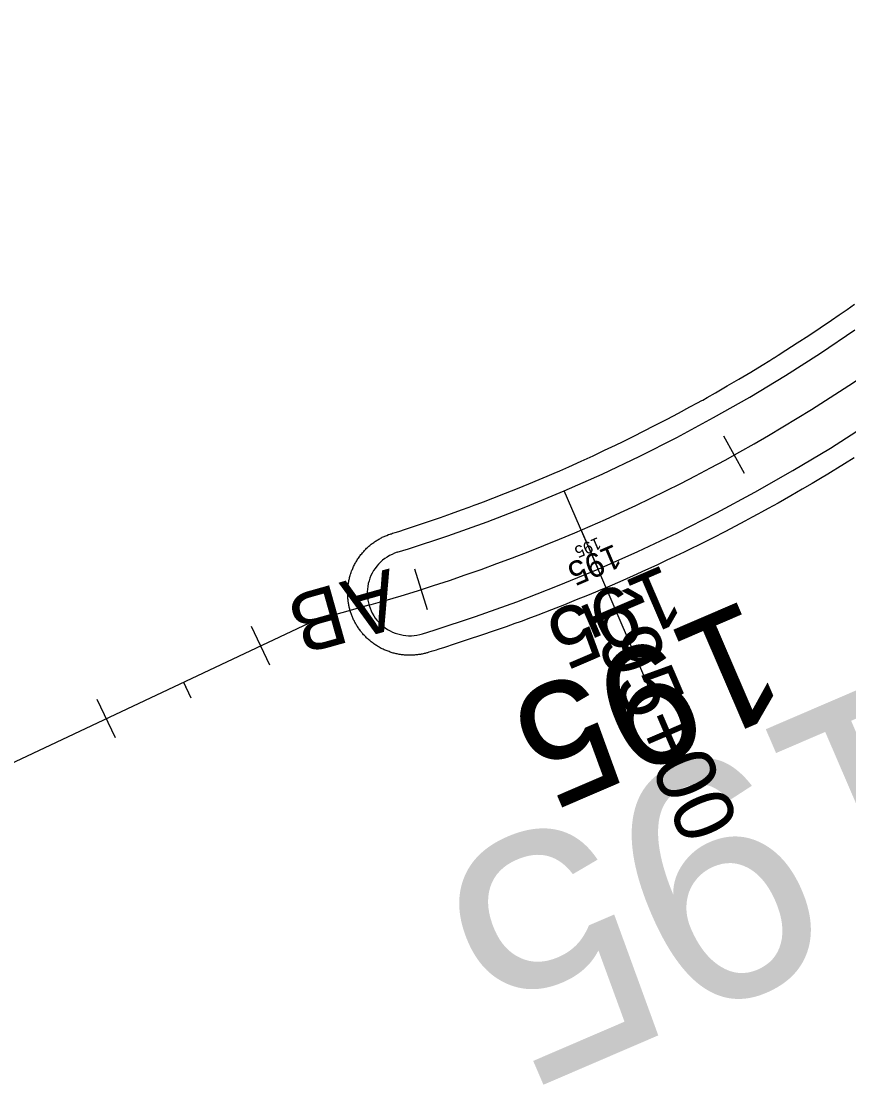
# Model space of a CAD drawing. Extents: x 1823824 to 1861612, y 706975 to 726130.
# Drawn here: x 1825801.7 to 1825898.7, y 712728.7 to 712853.4 of the extents above; entities that cross this region are included whole.
import ezdxf

# ---------------------------------------------------------------- set-up
doc = ezdxf.new("R2010")
doc.units = 0
for name, color, linetype in [('DR_X_Flood_Boundary', 7, 'Continuous'), ('GE_X_CL_10', 7, 'Continuous'), ('GE_X_CL_100', 7, 'Continuous'), ('GE_X_CL_20', 7, 'Continuous'), ('GE_X_CL_200', 7, 'Continuous'), ('GE_X_CL_50', 7, 'Continuous'), ('SC_Scratch2', 7, 'Continuous'), ('SC_Scratch5', 7, 'Continuous'), ('SC_Scratch6', 7, 'Continuous')]:
    doc.layers.add(name, color=color, linetype=linetype)

msp = doc.modelspace()

# ---------------------------------------------------------------- linework, layer by layer
at = {"layer": 'DR_X_Flood_Boundary'}
for p, q in [((1825842.46, 712784.93), (1825836.12, 712783.15)), ((1825836.12, 712783.15), (1825768.62, 712751.29))]:
    msp.add_line(p, q, dxfattribs=at)
msp.add_arc((1825788.29, 712977.46), 200, 285.7144, 321.6626, dxfattribs=at)
at = {"layer": 'GE_X_CL_10'}
for p, q in [((1825867.32, 712793.74), (1825867.72, 712792.82)), ((1825820.73, 712775.89), (1825821.15, 712774.98))]:
    msp.add_line(p, q, dxfattribs=at)
at = {"layer": 'GE_X_CL_100'}
msp.add_line((1825867.32, 712793.74), (1825871.27, 712784.55), dxfattribs=at)
at = {"layer": 'GE_X_CL_20'}
for p, q in [((1825867.32, 712793.74), (1825868.11, 712791.9)), ((1825820.73, 712775.89), (1825821.58, 712774.08))]:
    msp.add_line(p, q, dxfattribs=at)
at = {"layer": 'GE_X_CL_200'}
msp.add_line((1825867.32, 712793.74), (1825875.22, 712775.36), dxfattribs=at)
at = {"layer": 'GE_X_CL_50'}
msp.add_line((1825867.32, 712793.74), (1825869.3, 712789.14), dxfattribs=at)
at = {"layer": 'SC_Scratch2'}
for p, q in [((1825896.53, 712803.36), (1825900.85, 712806.12)), ((1825892.14, 712800.71), (1825896.53, 712803.36)), ((1825887.69, 712798.17), (1825892.14, 712800.71)), ((1825883.18, 712795.74), (1825887.69, 712798.17)), ((1825878.61, 712793.43), (1825883.18, 712795.74)), ((1825873.98, 712791.23), (1825878.61, 712793.43)), ((1825869.3, 712789.14), (1825873.98, 712791.23)), ((1825864.56, 712787.18), (1825869.3, 712789.14)), ((1825859.78, 712785.33), (1825864.56, 712787.18)), ((1825854.96, 712783.6), (1825859.78, 712785.33)), ((1825850.09, 712782), (1825854.96, 712783.6)), ((1825848.73, 712781.57), (1825850.09, 712782))]:
    msp.add_line(p, q, dxfattribs=at)
for points in [[(1825844.75, 712793.2), (1825844.96, 712793.27), (1825845.03, 712793.29), (1825845.07, 712793.31), (1825845.09, 712793.31), (1825845.24, 712793.36), (1825845.52, 712793.45), (1825845.95, 712793.59), (1825846.74, 712793.85), (1825847.9, 712794.23), (1825849.43, 712794.74), (1825850.84, 712795.22), (1825852.13, 712795.67), (1825853.3, 712796.1), (1825854.19, 712796.42), (1825854.81, 712796.64), (1825855.15, 712796.77), (1825855.87, 712797.04), (1825856.98, 712797.47), (1825858.47, 712798.05), (1825859.88, 712798.61), (1825861.2, 712799.15), (1825862.42, 712799.67), (1825863.33, 712800.05), (1825863.9, 712800.29), (1825864.16, 712800.4), (1825864.81, 712800.69), (1825865.88, 712801.16), (1825867.34, 712801.82), (1825868.74, 712802.46), (1825870.08, 712803.09), (1825871.35, 712803.7), (1825872.26, 712804.13), (1825872.8, 712804.39), (1825872.97, 712804.47), (1825873.56, 712804.77), (1825874.57, 712805.29), (1825876, 712806.02), (1825877.4, 712806.74), (1825878.75, 712807.46), (1825880.06, 712808.17), (1825880.97, 712808.67), (1825881.48, 712808.94), (1825881.57, 712808.99), (1825882.1, 712809.29), (1825883.06, 712809.84), (1825884.45, 712810.64), (1825885.82, 712811.45), (1825887.19, 712812.27), (1825888.54, 712813.09), (1825889.44, 712813.64), (1825889.91, 712813.92), (1825889.93, 712813.93), (1825890.39, 712814.23), (1825891.3, 712814.82), (1825892.65, 712815.68), (1825893.99, 712816.56), (1825895.32, 712817.46), (1825896.65, 712818.36), (1825897.54, 712818.97), (1825898.01, 712819.28), (1825898.04, 712819.3), (1825898.48, 712819.62), (1825899.34, 712820.24)], [(1825845.78, 712791.13), (1825847.08, 712791.53), (1825851.71, 712793.06), (1825856.3, 712794.7), (1825860.84, 712796.46), (1825865.35, 712798.33), (1825869.8, 712800.31), (1825874.2, 712802.4), (1825878.55, 712804.61), (1825882.84, 712806.92), (1825887.08, 712809.33), (1825891.25, 712811.86), (1825895.36, 712814.48), (1825899.4, 712817.21)], [(1825899.31, 712802.21), (1825898.18, 712801.5), (1825897.36, 712800.99), (1825896.87, 712800.69), (1825896.21, 712800.3), (1825895.38, 712799.8), (1825894.4, 712799.21), (1825893.24, 712798.53), (1825891.9, 712797.76), (1825890.4, 712796.91), (1825889.25, 712796.27), (1825888.46, 712795.83), (1825888.03, 712795.59), (1825887.37, 712795.24), (1825886.5, 712794.78), (1825885.41, 712794.2), (1825884.17, 712793.55), (1825882.78, 712792.84), (1825881.24, 712792.06), (1825880.08, 712791.49), (1825879.32, 712791.11), (1825878.95, 712790.94), (1825878.3, 712790.63), (1825877.38, 712790.2), (1825876.19, 712789.64), (1825874.87, 712789.03), (1825873.42, 712788.38), (1825871.84, 712787.68), (1825870.68, 712787.17), (1825869.96, 712786.86), (1825869.65, 712786.73), (1825869.02, 712786.47), (1825868.06, 712786.07), (1825866.76, 712785.54), (1825865.36, 712784.98), (1825863.85, 712784.39), (1825862.24, 712783.77), (1825861.09, 712783.33), (1825860.4, 712783.07), (1825860.17, 712782.99), (1825859.55, 712782.77), (1825858.54, 712782.41), (1825857.14, 712781.92), (1825855.66, 712781.41), (1825854.1, 712780.89)], [(1825840.45, 712783.74), (1825840.41, 712783.84), (1825840.37, 712783.94), (1825840.34, 712784.05), (1825840.3, 712784.15), (1825840.27, 712784.25), (1825840.24, 712784.36), (1825840.21, 712784.46), (1825840.19, 712784.57), (1825840.16, 712784.68), (1825840.13, 712784.78), (1825840.11, 712784.89), (1825840.09, 712785), (1825840.07, 712785.11), (1825840.05, 712785.23), (1825840.04, 712785.34), (1825840.02, 712785.45), (1825840.01, 712785.56), (1825840, 712785.67), (1825839.99, 712785.75), (1825839.98, 712785.79), (1825839.98, 712785.79), (1825839.98, 712785.83), (1825839.98, 712785.91), (1825839.97, 712786.03), (1825839.97, 712786.15), (1825839.97, 712786.26), (1825839.96, 712786.38), (1825839.97, 712786.5), (1825839.97, 712786.62), (1825839.98, 712786.74), (1825839.98, 712786.86), (1825839.99, 712786.98), (1825840, 712787.1), (1825840.02, 712787.22), (1825840.03, 712787.34), (1825840.05, 712787.46), (1825840.07, 712787.58), (1825840.09, 712787.7), (1825840.12, 712787.83), (1825840.14, 712787.95), (1825840.17, 712788.07), (1825840.2, 712788.19), (1825840.23, 712788.31), (1825840.27, 712788.43), (1825840.3, 712788.55), (1825840.34, 712788.66), (1825840.38, 712788.78), (1825840.43, 712788.9), (1825840.47, 712789.02), (1825840.52, 712789.13), (1825840.57, 712789.25), (1825840.62, 712789.36), (1825840.67, 712789.48), (1825840.73, 712789.59), (1825840.78, 712789.7), (1825840.84, 712789.82), (1825840.9, 712789.93), (1825840.96, 712790.03), (1825841.03, 712790.14), (1825841.1, 712790.25), (1825841.16, 712790.35), (1825841.23, 712790.46), (1825841.31, 712790.56), (1825841.38, 712790.66), (1825841.45, 712790.76), (1825841.53, 712790.86), (1825841.61, 712790.96), (1825841.69, 712791.06), (1825841.77, 712791.15), (1825841.85, 712791.24), (1825841.93, 712791.33), (1825842.02, 712791.42), (1825842.11, 712791.51), (1825842.19, 712791.6), (1825842.28, 712791.68), (1825842.37, 712791.76), (1825842.46, 712791.84), (1825842.56, 712791.92), (1825842.65, 712792), (1825842.74, 712792.08), (1825842.84, 712792.15), (1825842.93, 712792.22), (1825843.03, 712792.29), (1825843.13, 712792.36), (1825843.23, 712792.43), (1825843.32, 712792.49), (1825843.42, 712792.55), (1825843.52, 712792.61), (1825843.62, 712792.67), (1825843.73, 712792.73), (1825843.83, 712792.78), (1825843.93, 712792.84), (1825844.03, 712792.89), (1825844.13, 712792.94), (1825844.24, 712792.99), (1825844.34, 712793.03), (1825844.44, 712793.08), (1825844.54, 712793.12), (1825844.75, 712793.2)], [(1825854.1, 712780.89), (1825852.45, 712780.35), (1825851.31, 712779.98), (1825850.67, 712779.77), (1825850.52, 712779.72), (1825850.32, 712779.66), (1825850.06, 712779.58), (1825849.74, 712779.48), (1825849.49, 712779.41), (1825849.33, 712779.35), (1825849.23, 712779.33), (1825849.14, 712779.3), (1825849.04, 712779.28), (1825848.93, 712779.25), (1825848.82, 712779.23), (1825848.71, 712779.2), (1825848.6, 712779.18), (1825848.49, 712779.16), (1825848.38, 712779.14), (1825848.27, 712779.13), (1825848.16, 712779.11), (1825848.04, 712779.1), (1825847.93, 712779.09), (1825847.81, 712779.08), (1825847.7, 712779.07), (1825847.58, 712779.06), (1825847.46, 712779.06), (1825847.34, 712779.06), (1825847.23, 712779.06), (1825847.11, 712779.06), (1825846.99, 712779.06), (1825846.87, 712779.07), (1825846.75, 712779.07), (1825846.63, 712779.08), (1825846.51, 712779.1), (1825846.39, 712779.11), (1825846.26, 712779.12), (1825846.14, 712779.14), (1825846.02, 712779.16), (1825845.9, 712779.18), (1825845.78, 712779.21), (1825845.66, 712779.23), (1825845.54, 712779.26), (1825845.42, 712779.29), (1825845.3, 712779.32), (1825845.18, 712779.36), (1825845.06, 712779.4), (1825844.94, 712779.43), (1825844.82, 712779.48), (1825844.71, 712779.52), (1825844.59, 712779.56), (1825844.47, 712779.61), (1825844.36, 712779.66), (1825844.24, 712779.71), (1825844.13, 712779.76), (1825844.02, 712779.82), (1825843.9, 712779.87), (1825843.79, 712779.93), (1825843.68, 712779.99), (1825843.57, 712780.06), (1825843.46, 712780.12), (1825843.36, 712780.19), (1825843.25, 712780.26), (1825843.15, 712780.33), (1825843.04, 712780.4), (1825842.94, 712780.47), (1825842.84, 712780.55), (1825842.74, 712780.62), (1825842.65, 712780.7), (1825842.55, 712780.78), (1825842.46, 712780.86), (1825842.36, 712780.94), (1825842.27, 712781.03), (1825842.18, 712781.11), (1825842.1, 712781.2), (1825842.01, 712781.29), (1825841.93, 712781.37), (1825841.84, 712781.46), (1825841.76, 712781.56), (1825841.68, 712781.65), (1825841.61, 712781.74), (1825841.53, 712781.83), (1825841.46, 712781.93), (1825841.38, 712782.03), (1825841.31, 712782.12), (1825841.25, 712782.22), (1825841.18, 712782.32), (1825841.12, 712782.42), (1825841.05, 712782.52), (1825840.99, 712782.62), (1825840.93, 712782.72), (1825840.88, 712782.82), (1825840.82, 712782.92), (1825840.77, 712783.02), (1825840.72, 712783.12), (1825840.67, 712783.22), (1825840.62, 712783.33), (1825840.57, 712783.43), (1825840.53, 712783.53), (1825840.49, 712783.64), (1825840.45, 712783.74)]]:
    msp.add_lwpolyline(points, dxfattribs=at)
msp.add_arc((1825847.26, 712786.35), 5, 107.1437, 287.1451, dxfattribs=at)
at = {"layer": 'SC_Scratch5'}
for points in [[(1825886.48, 712800.36), (1825884.06, 712804.73)], [(1825869.3, 712789.14), (1825865.35, 712798.33)], [(1825849.34, 712784.38), (1825847.83, 712789.15)], [(1825830.84, 712777.89), (1825828.7, 712782.42)], [(1825812.75, 712769.36), (1825810.62, 712773.88)]]:
    msp.add_lwpolyline(points, dxfattribs=at)

# ---------------------------------------------------------------- texts
at = {"layer": 'GE_X_CL_10'}
msp.add_text('195', height=1.4, rotation=203.2757, dxfattribs=at).set_placement((1825869.28, 712792.94))
at = {"layer": 'GE_X_CL_100'}
msp.add_text('195', height=14, rotation=203.2757, dxfattribs=at).set_placement((1825886.86, 712785.81))
at = {"layer": 'GE_X_CL_20'}
msp.add_text('195', height=2.8, rotation=203.2757, dxfattribs=at).set_placement((1825871.23, 712792.15))
at = {"layer": 'GE_X_CL_200'}
msp.add_text('195', height=28, rotation=203.2757, dxfattribs=at).set_placement((1825906.41, 712777.89))
at = {"layer": 'GE_X_CL_50'}
msp.add_text('195', height=7, rotation=203.2757, dxfattribs=at).set_placement((1825877.09, 712789.77))
at = {"layer": 'SC_Scratch5'}
msp.add_text('195+00', height=7, rotation=293.2757, dxfattribs=at).set_placement((1825867.07, 712785.46))
at = {"layer": 'SC_Scratch6'}
for s, p in [('A', (1825844.88, 712789.25)), ('B', (1825838.54, 712787.47))]:
    msp.add_text(s, height=7, rotation=195.7144, dxfattribs=at).set_placement(p)

doc.saveas('drawing.dxf')
